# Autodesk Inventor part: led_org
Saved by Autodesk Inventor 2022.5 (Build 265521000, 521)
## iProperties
Created: 2024-12
Part Number: led_org
Material: Generic
Document SubType Name: Modeling
Designer: AdminForWorker
Density: 1 g/cm^3
Appearance: Default
Title: led_org
Author: AdminForWorker
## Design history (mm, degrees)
feature "Body11"
feature "Body8"
body "Solid1"
body "Solid2"
